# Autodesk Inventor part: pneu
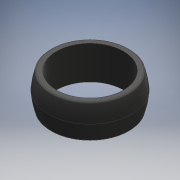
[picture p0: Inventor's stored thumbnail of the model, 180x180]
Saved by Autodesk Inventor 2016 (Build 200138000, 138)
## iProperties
Created: 2018-03
Part Number: pneu
Material: Générique
Document SubType Name: Modeling
Designer: Bruno
Density: 1 g/cm^3
Appearance: Caoutchouc - Noir
Author: Bruno
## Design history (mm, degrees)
sketch "Esquisse1"
  geometry: L1 (0, 0)-(26, 0); L2 (26, 0)-(26, 13); L3 (26, 13)-(29.276, 13); L4 (0, 0)-(0, -3.07); L5 (32.5, 0.755)-(32.5, -1.085); L6 (32.5, 0)-(26, 0); A1 r 49.101 centre (-16.527, -2.688) between (32.5, 0) and (30.228, 12.305); A2 r 1 centre (29.276, 12) between (30.228, 12.305) and (29.276, 13); 1 further point
  constraints: 12 end point, 5 point on circle, 3 perpendicular, 2 centre point, 2 point on line, 2 tangent, 2 vertical, 1 horizontal
  dimensions: "d0" = 26 distance of L1.start L1.end; "d1" = 13 distance of L1.end L2.end; "d2" = 4 distance of L2.end point (30, 13); "d3" = 32.5 distance between parallel lines of L5 L4; "d4" = 1 radius of A2
revolve "Révolution1" sketch "Esquisse1" stored, may be unused: angle "d5" = 90 deg
mirror "Symétrie1"
node "Solide1"
